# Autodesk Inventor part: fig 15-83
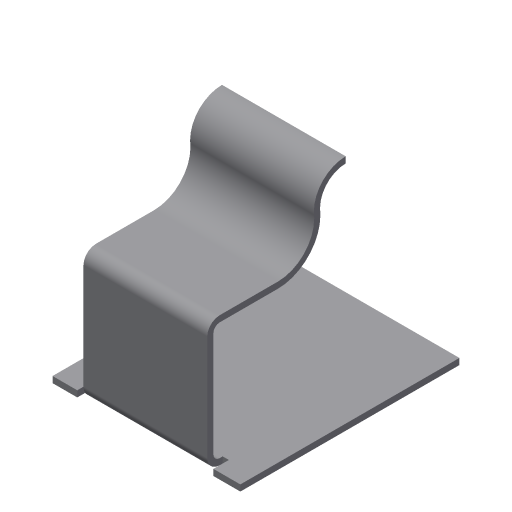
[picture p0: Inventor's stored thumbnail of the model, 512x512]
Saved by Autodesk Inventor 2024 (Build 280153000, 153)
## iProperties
Shininess: 77.0
Angle Display Precision: 2
Document Length Units: 11269
Document Angle Units: 11279
Document Time Units: 11290
Document Mass Units: 11283
Document Length Units Precision: 3
Document Angle Units Precision: 2
Compacted: True
Created: 2002-04
Part Number: fig 15-83
Document SubType Name: Sheet Metal
Density: 1 g/cm^3
Sheet Metal Rule: Default
Material: Generic
Appearance: Default
Density: 0.0
Volumn: 0.0
Area: 0.0
PropertySet Name: Model Information
Control State: 0
Master: False
Checked Out: False
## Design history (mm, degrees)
node "Face1"
  sketch "Sketch1"
    geometry: L1 (-24.824, 17.882)-(5.529, 17.882); L2 (5.529, 17.882)-(5.529, -17.529); L3 (5.529, -17.529)-(-24.824, -17.529); L4 (-24.824, -17.529)-(-24.824, 17.882)
    constraints: 8 end point, 2 parallel, 1 horizontal, 1 perpendicular
node "Flange1"
node "Contour Flange6"
  sketch "Sketch5"
    geometry: L1 (0, 1)-(0, 11.431); A1 r 5.855 centre (-5.855, 11.431) between (0, 11.431) and (-6.422, 17.259); A2 r 5.142 centre (-6.92, 22.376) between (-12.062, 22.382) and (-6.422, 17.259)
    constraints: 4 point on circle, 2 centre point, 2 end point, 2 tangent
body "Solid1"
face "Plate1" dims "d42" = 1 (= Thickness)
sketch "Sketch3"
  geometry: L1 (25.353, 0)-(5.353, 0); L2 (5.353, 0)-(5.353, 20); L3 (5.353, 20)-(25.353, 20); L4 (25.353, 20)-(25.353, 0)
  constraints: 8 end point
face "Plate3" dims "d5" = 20, "d6" = 90 deg, "d7" = 1 (= BendRadius), "d11" = 5, "d12" = 20, "d42" = 1 (= Thickness), "MinimumRemnant" = 2 (= 2 x Thickness), "BendReliefWidth" = 1 (= Thickness)
bend "Bend2" dims "d5" = 20, "d6" = 90 deg, "d7" = 1 (= BendRadius), "d21" = 1 (= BendReliefWidth), "d22" = 0.5 (= BendReliefDepth), "d23" = 2 (= MinimumRemnant), "d42" = 1 (= Thickness), "SeamGap" = 0.01, "MinimumRemnant" = 2 (= 2 x Thickness), "BendReliefWidth" = 1 (= Thickness), "TransitionRadius" = 1 (= BendRadius)
face "Plate8" dims "d33" = 1 (= BendReliefWidth), "d34" = 0.5 (= BendReliefDepth), "d35" = 2 (= MinimumRemnant), "d36" = 1 (= BendRadius), "d37" = 1 (= BendRadius), "d38" = 1, "d39" = 4 (= CornerReliefSize), "d40" = 1 (= GapSize), "d41" = 1 (= JacobiRadiusSize), "d42" = 1 (= Thickness), "SeamGap" = 0.01
bend "Bend7" dims "d33" = 1 (= BendReliefWidth), "d34" = 0.5 (= BendReliefDepth), "d35" = 2 (= MinimumRemnant), "d36" = 1 (= BendRadius), "d37" = 1 (= BendRadius), "d38" = 1, "d42" = 1 (= Thickness), "SeamGap" = 0.01
feature "Corner1" dims "d38" = 1, "d39" = 4 (= CornerReliefSize), "d40" = 1 (= GapSize), "d41" = 1 (= JacobiRadiusSize)
other parameters: "Thickness" = 1, "BendRadius" = 1 (= Thickness), "BendReliefDepth" = 0.5 (= 0.5 x Thickness), "CornerReliefSize" = 4 (= 4 x Thickness), "d0" = 1 (= BendRadius), "d4" = 1 (= BendRadius), "JacobiRadiusSize" = 1 (= Thickness), "GapSize" = 1 (= Thickness)
